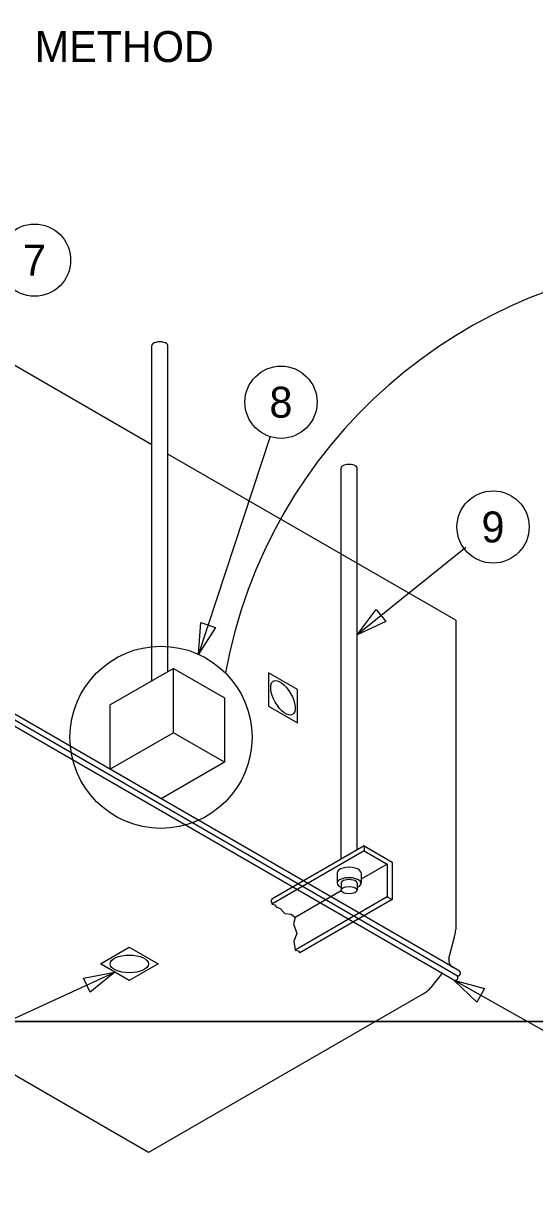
# Model space of a CAD drawing. Extents: x 10110.2 to 10159.4, y 10049.5 to 10140.5.
# Drawn here: x 10131.09 to 10142.12, y 10091.33 to 10116.52 of the extents above; entities that cross this region are included whole.
import ezdxf

# ---------------------------------------------------------------- set-up
doc = ezdxf.new("R2010")
doc.units = 0
for name, color, linetype in [('G-ANNO-SYMB', 7, 'Continuous'), ('G-DETL-GRID', 7, 'Continuous'), ('G-DETL-LINE', 7, 'Continuous'), ('G-DETL-TEXT', 7, 'Continuous')]:
    doc.layers.add(name, color=color, linetype=linetype)

msp = doc.modelspace()

# ---------------------------------------------------------------- linework, layer by layer
at = {"layer": 'G-ANNO-SYMB'}
for centre in [(10131.334, 10111.419), (10136.65, 10108.356), (10141.223, 10105.666)]:
    msp.add_circle(centre, 0.779, dxfattribs=at)
at = {"layer": 'G-DETL-GRID'}
for points in [[(10110.22, 10140.505), (10159.362, 10140.505), (10159.362, 10095.005), (10110.22, 10095.005)], [(10110.22, 10095.005), (10159.362, 10095.005), (10159.362, 10049.505), (10110.22, 10049.505)]]:
    msp.add_lwpolyline(points, close=True, dxfattribs=at)
at = {"layer": 'G-DETL-LINE'}
for p, q in [((10133.865, 10107.438), (10127.497, 10111.115)), ((10133.865, 10107.438), (10127.497, 10111.115)), ((10133.865, 10102.349), (10133.865, 10109.577)), ((10133.865, 10102.349), (10133.865, 10109.577)), ((10134.21, 10102.549), (10134.21, 10109.577)), ((10134.21, 10102.549), (10134.21, 10109.577)), ((10140.417, 10103.656), (10134.21, 10107.239)), ((10140.417, 10103.656), (10134.21, 10107.239)), ((10137.944, 10105.083), (10137.944, 10106.935)), ((10137.944, 10105.083), (10137.944, 10106.935)), ((10138.289, 10104.884), (10138.289, 10106.935)), ((10138.289, 10104.884), (10138.289, 10106.935)), ((10137.944, 10098.502), (10137.944, 10105.083)), ((10137.944, 10098.502), (10137.944, 10105.083)), ((10138.289, 10098.701), (10138.289, 10104.884)), ((10138.289, 10098.701), (10138.289, 10104.884)), ((10140.417, 10103.656), (10140.417, 10096.984)), ((10140.417, 10103.656), (10140.417, 10096.984)), ((10140.435, 10095.995), (10127.807, 10103.286)), ((10140.435, 10095.995), (10127.807, 10103.286)), ((10140.493, 10096.095), (10127.921, 10103.353)), ((10140.493, 10096.095), (10127.921, 10103.353)), ((10140.378, 10095.896), (10127.692, 10103.22)), ((10140.378, 10095.896), (10127.692, 10103.22)), ((10134.329, 10102.617), (10132.964, 10101.829)), ((10134.329, 10102.617), (10132.964, 10101.829)), ((10132.964, 10100.442), (10132.964, 10101.829)), ((10132.964, 10100.442), (10132.964, 10101.829)), ((10134.329, 10101.23), (10132.964, 10100.442)), ((10134.329, 10101.23), (10132.964, 10100.442)), ((10135.433, 10100.592), (10134.068, 10099.804)), ((10135.433, 10100.592), (10134.068, 10099.804)), ((10134.068, 10099.804), (10132.964, 10100.442)), ((10134.068, 10099.804), (10132.964, 10100.442)), ((10133.792, 10092.181), (10121.181, 10099.461)), ((10133.792, 10092.181), (10121.181, 10099.461)), ((10138.44, 10098.789), (10136.452, 10097.641)), ((10138.44, 10098.789), (10136.452, 10097.641)), ((10138.44, 10098.789), (10139.045, 10098.44)), ((10138.44, 10098.789), (10138.44, 10098.684)), ((10138.44, 10098.789), (10139.045, 10098.44)), ((10138.44, 10098.789), (10138.44, 10098.684)), ((10138.44, 10098.684), (10136.452, 10097.536)), ((10138.44, 10098.684), (10136.452, 10097.536)), ((10138.44, 10098.684), (10138.94, 10098.396)), ((10138.44, 10098.684), (10138.94, 10098.396)), ((10138.94, 10098.396), (10138.375, 10098.07)), ((10138.94, 10098.396), (10138.375, 10098.07)), ((10138.94, 10098.396), (10138.94, 10097.69)), ((10138.94, 10098.396), (10138.94, 10097.69)), ((10139.045, 10098.44), (10139.045, 10097.63)), ((10139.045, 10098.44), (10139.045, 10097.63)), ((10137.858, 10098.209), (10137.858, 10097.984)), ((10137.858, 10098.209), (10137.858, 10097.984)), ((10138.375, 10098.209), (10138.375, 10097.984)), ((10138.375, 10098.209), (10138.375, 10097.984)), ((10137.946, 10097.822), (10136.952, 10097.248)), ((10137.946, 10097.822), (10136.952, 10097.248)), ((10137.944, 10097.984), (10137.944, 10097.834)), ((10137.944, 10097.984), (10137.944, 10097.834)), ((10138.289, 10097.984), (10138.289, 10097.834)), ((10138.289, 10097.984), (10138.289, 10097.834)), ((10136.452, 10097.641), (10136.433, 10097.588)), ((10136.452, 10097.641), (10136.433, 10097.588)), ((10136.433, 10097.588), (10136.449, 10097.563)), ((10136.433, 10097.588), (10136.449, 10097.563)), ((10136.449, 10097.563), (10136.463, 10097.547)), ((10136.449, 10097.563), (10136.463, 10097.547)), ((10136.463, 10097.547), (10136.452, 10097.536)), ((10136.463, 10097.547), (10136.452, 10097.536)), ((10136.452, 10097.536), (10136.514, 10097.519)), ((10136.452, 10097.536), (10136.514, 10097.519)), ((10136.514, 10097.519), (10136.543, 10097.473)), ((10136.514, 10097.519), (10136.543, 10097.473)), ((10138.94, 10097.69), (10136.952, 10096.542)), ((10138.94, 10097.69), (10136.952, 10096.542)), ((10139.045, 10097.63), (10137.056, 10096.482)), ((10139.045, 10097.63), (10137.056, 10096.482)), ((10138.94, 10097.69), (10139.045, 10097.63)), ((10138.94, 10097.69), (10139.045, 10097.63)), ((10136.543, 10097.473), (10136.634, 10097.443)), ((10136.543, 10097.473), (10136.634, 10097.443)), ((10136.634, 10097.443), (10136.733, 10097.335)), ((10136.634, 10097.443), (10136.733, 10097.335)), ((10136.733, 10097.335), (10136.866, 10097.318)), ((10136.733, 10097.335), (10136.866, 10097.318)), ((10136.866, 10097.318), (10136.952, 10097.248)), ((10136.866, 10097.318), (10136.952, 10097.248)), ((10136.952, 10097.248), (10136.921, 10097.107)), ((10136.952, 10097.248), (10136.921, 10097.107)), ((10136.921, 10097.107), (10136.989, 10096.903)), ((10136.921, 10097.107), (10136.989, 10096.903)), ((10136.989, 10096.903), (10136.928, 10096.732)), ((10136.989, 10096.903), (10136.928, 10096.732)), ((10136.928, 10096.732), (10136.952, 10096.542)), ((10136.928, 10096.732), (10136.952, 10096.542)), ((10140.272, 10096.363), (10140.401, 10096.858)), ((10140.272, 10096.363), (10140.401, 10096.858)), ((10136.952, 10096.542), (10137.02, 10096.524)), ((10136.952, 10096.542), (10137.02, 10096.524)), ((10137.02, 10096.524), (10137.056, 10096.482)), ((10137.02, 10096.524), (10137.056, 10096.482)), ((10140.125, 10096.042), (10139.884, 10095.739)), ((10140.125, 10096.042), (10139.884, 10095.739)), ((10139.742, 10095.616), (10133.792, 10092.181)), ((10139.742, 10095.616), (10133.792, 10092.181))]:
    msp.add_line(p, q, dxfattribs=at)
for points in [[(10135.433, 10100.592), (10134.329, 10101.23), (10134.329, 10102.617), (10135.433, 10101.98)], [(10135.433, 10100.592), (10134.329, 10101.23), (10134.329, 10102.617), (10135.433, 10101.98)], [(10136.379, 10102.521), (10136.379, 10101.803), (10137.002, 10101.443), (10137.002, 10102.162)], [(10136.379, 10102.521), (10136.379, 10101.803), (10137.002, 10101.443), (10137.002, 10102.162)], [(10132.757, 10096.245), (10133.378, 10096.603), (10133.999, 10096.245), (10133.378, 10095.886)], [(10132.757, 10096.245), (10133.378, 10096.603), (10133.999, 10096.245), (10133.378, 10095.886)]]:
    msp.add_lwpolyline(points, close=True, dxfattribs=at)
for centre, radius, start, end in [((10139.917, 10096.984), 0.5, 345.3954, 0), ((10139.917, 10096.984), 0.5, 345.3954, 0), ((10140.433, 10096.321), 0.167, 165.3951, 240), ((10140.433, 10096.321), 0.167, 165.3951, 240), ((10140.407, 10095.946), 0.0573, 239.9993, 59.9993), ((10140.407, 10095.946), 0.0573, 239.9993, 59.9993), ((10140.464, 10096.045), 0.0573, 239.9993, 59.9993), ((10140.464, 10096.045), 0.0573, 239.9993, 59.9993), ((10139.492, 10096.049), 0.5, 300, 321.6154), ((10139.492, 10096.049), 0.5, 300, 321.6154)]:
    msp.add_arc(centre, radius, start, end, dxfattribs=at)
for centre, major_axis, start_param, end_param in [((10134.038, 10109.578), (-0.173, 0), 3.137491, 6.287287), ((10134.038, 10109.578), (-0.173, 0), 3.137491, 6.287287), ((10138.117, 10106.935), (-0.173, 0), 3.137491, 6.287287), ((10138.117, 10106.935), (-0.173, 0), 3.137491, 6.287287), ((10138.117, 10098.209), (-0.259, 0), 3.137491, 6.287287), ((10138.117, 10098.209), (-0.259, 0), 3.137491, 6.287287), ((10138.117, 10097.984), (-0.259, 0), 2.300516, 7.124262), ((10138.117, 10097.984), (-0.259, 0), 2.300516, 7.124262), ((10138.117, 10097.984), (-0.173, 0), 3.137491, 6.287287), ((10138.117, 10097.984), (-0.173, 0), 3.137491, 6.287287)]:
    msp.add_ellipse(centre, major_axis=major_axis, ratio=0.460797, start_param=start_param, end_param=end_param, dxfattribs=at)
for centre, major_axis, ratio in [((10136.691, 10101.982), (-0.207, 0.359), 0.461166), ((10136.691, 10101.982), (-0.207, 0.359), 0.461166), ((10138.117, 10097.834), (-0.173, 0), 0.460797), ((10138.117, 10097.834), (-0.173, 0), 0.460797), ((10133.378, 10096.245), (-0.413, 0), 0.460797), ((10133.378, 10096.245), (-0.413, 0), 0.460797)]:
    msp.add_ellipse(centre, major_axis=major_axis, ratio=ratio, dxfattribs=at)
at = {"layer": 'G-DETL-TEXT'}
for p, q in [((10136.417, 10107.619), (10134.869, 10102.921)), ((10140.639, 10105.224), (10138.289, 10103.339)), ((10127.445, 10093.492), (10133.067, 10096.065)), ((10142.329, 10094.794), (10140.378, 10095.896))]:
    msp.add_line(p, q, dxfattribs=at)
for points in [[(10138.914, 10103.626), (10138.289, 10103.339), (10138.705, 10103.886)], [(10138.914, 10103.626), (10138.289, 10103.339), (10138.705, 10103.886)], [(10135.236, 10103.502), (10134.869, 10102.921), (10134.919, 10103.606)], [(10135.236, 10103.502), (10134.869, 10102.921), (10134.919, 10103.606)], [(10132.392, 10095.939), (10133.067, 10096.065), (10132.531, 10095.636)], [(10132.392, 10095.939), (10133.067, 10096.065), (10132.531, 10095.636)], [(10140.876, 10095.423), (10140.378, 10095.896), (10141.04, 10095.713)]]:
    msp.add_lwpolyline(points, close=True, dxfattribs=at)
msp.add_circle((10134.061, 10101.131), 1.964, dxfattribs=at)
msp.add_arc((10146.103, 10100.578), 10.828, 92.6951, 169.6737, dxfattribs=at)
msp.add_arc((10146.103, 10100.578), 10.828, 92.6951, 169.6737, dxfattribs=at)

# ---------------------------------------------------------------- texts
at = {"layer": 'G-ANNO-SYMB'}
for s, p in [('7', (10131.084, 10111.086)), ('8', (10136.4, 10108.023)), ('9', (10140.973, 10105.333))]:
    msp.add_text(s, height=0.667, dxfattribs=at).set_placement(p)
at = {"layer": 'G-DETL-TEXT'}
msp.add_text('METHOD', height=0.6667, dxfattribs=at).set_placement((10131.338, 10115.691))

doc.saveas('drawing.dxf')
